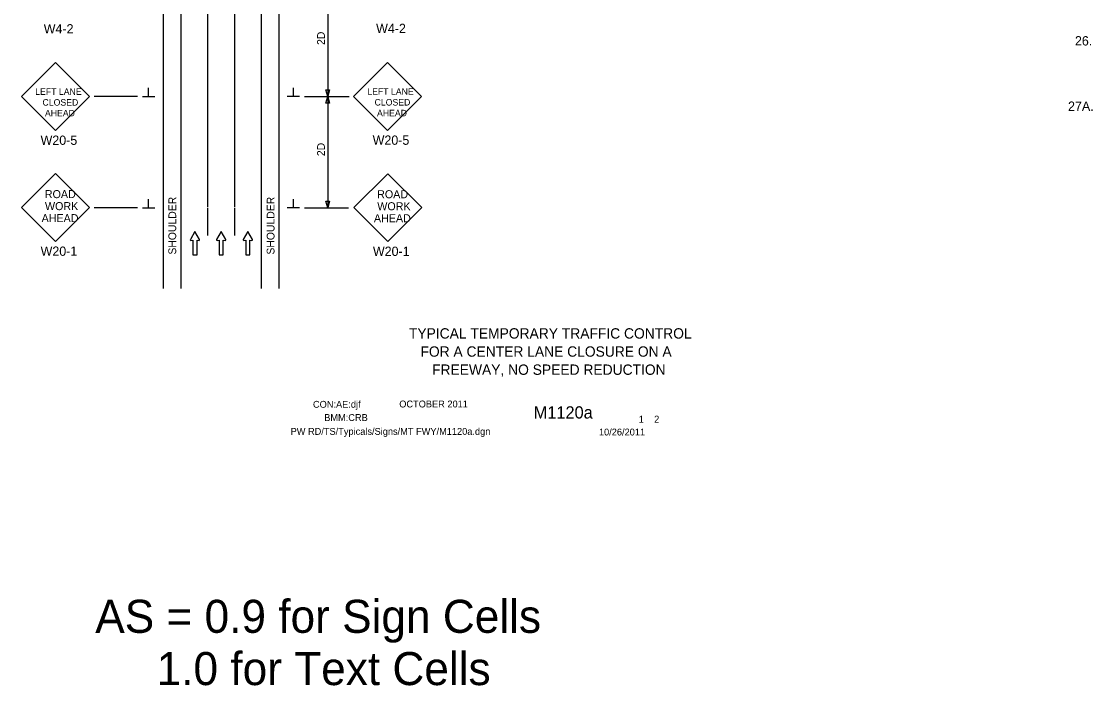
# Model space of a CAD drawing. Extents: x 16595 to 19519, y 6994 to 8256.
# Drawn here: x 16828 to 17792, y 6994 to 7592 of the extents above; entities that cross this region are included whole.
import ezdxf

# ---------------------------------------------------------------- set-up
doc = ezdxf.new("R2010")
doc.units = 0
for name, color, linetype in [('ALI_LEGAL_EX', 7, 'Continuous'), ('BORDER', 7, 'Continuous'), ('BORDER_SIGNAL_WO', 7, 'Continuous'), ('MT_SCRATCH_LEVEL_E', 7, 'Continuous'), ('PAVT_EDGE_EX', 7, 'Continuous'), ('TRAFFIC_SIGNS_PR', 7, 'Continuous'), ('TYPICAL_TEXT_DIMEN_PR', 7, 'Continuous')]:
    doc.layers.add(name, color=color, linetype=linetype)

msp = doc.modelspace()

# ---------------------------------------------------------------- linework, layer by layer
at = {"layer": 'ALI_LEGAL_EX'}
for p, q in [((16995.95, 8243.16), (16995.95, 7425.02)), ((17019.95, 8243.16), (17019.95, 7425.02))]:
    msp.add_line(p, q, dxfattribs=at)
for points in [[(16995.95, 7524.26), (16995.95, 7499.26)], [(17019.95, 7524.26), (17019.95, 7499.26)], [(16995.95, 7424.26), (16995.95, 7399.26)], [(17019.95, 7424.26), (17019.95, 7399.26)]]:
    msp.add_lwpolyline(points, dxfattribs=at)
at = {"layer": 'MT_SCRATCH_LEVEL_E'}
for p, q in [((16984.51, 7402.8), (16980.4, 7395.56)), ((16988.65, 7395.56), (16984.51, 7402.8)), ((17008.06, 7402.8), (17003.94, 7395.56)), ((17012.2, 7395.56), (17008.06, 7402.8)), ((17032.13, 7402.8), (17028.01, 7395.56)), ((17036.27, 7395.56), (17032.13, 7402.8)), ((16980.88, 7394.87), (16982.66, 7395.19)), ((16982.66, 7395.19), (16982.66, 7381.93)), ((16986.4, 7381.93), (16986.4, 7395.19)), ((16986.4, 7395.19), (16988.17, 7394.87)), ((17004.43, 7394.87), (17006.2, 7395.19)), ((17006.2, 7395.19), (17006.2, 7381.93)), ((17009.94, 7381.93), (17009.94, 7395.19)), ((17009.94, 7395.19), (17011.72, 7394.87)), ((17028.5, 7394.87), (17030.27, 7395.19)), ((17030.27, 7395.19), (17030.27, 7381.93)), ((17034.02, 7381.93), (17034.02, 7395.19)), ((17034.02, 7395.19), (17035.79, 7394.87)), ((16982.66, 7381.93), (16986.4, 7381.93)), ((17006.2, 7381.93), (17009.94, 7381.93)), ((17030.27, 7381.93), (17034.02, 7381.93))]:
    msp.add_line(p, q, dxfattribs=at)
for centre, start, end in [((16980.8, 7395.33), 150.42484, 279.96381), ((16988.25, 7395.33), 260.03619, 29.77312), ((17004.35, 7395.33), 150.42484, 279.96381), ((17011.79, 7395.33), 260.03619, 29.77312), ((17028.42, 7395.33), 150.42484, 279.96381), ((17035.86, 7395.33), 260.03619, 29.77312)]:
    msp.add_arc(centre, 0.463, start, end, dxfattribs=at)
at = {"layer": 'PAVT_EDGE_EX'}
for p, q in [((16955.95, 8212.14), (16955.95, 7351.67)), ((16971.95, 8212.14), (16971.95, 7351.67)), ((17043.95, 8212.14), (17043.95, 7351.67)), ((17059.95, 8212.14), (17059.95, 7351.67))]:
    msp.add_line(p, q, dxfattribs=at)
at = {"layer": 'TRAFFIC_SIGNS_PR'}
for p, q in [((16858.97, 7554.71), (16828.42, 7524.16)), ((16889.51, 7524.16), (16858.97, 7554.71)), ((17157.67, 7554.79), (17127.13, 7524.24)), ((17188.22, 7524.24), (17157.67, 7554.79)), ((16828.42, 7524.16), (16858.97, 7493.62)), ((16858.97, 7493.62), (16889.51, 7524.16)), ((17127.13, 7524.24), (17157.67, 7493.7)), ((17157.67, 7493.7), (17188.22, 7524.24)), ((16859, 7454.93), (16828.45, 7424.38)), ((16889.54, 7424.38), (16859, 7454.93)), ((17157.92, 7454.83), (17127.37, 7424.29)), ((17188.46, 7424.29), (17157.92, 7454.83)), ((16828.45, 7424.38), (16859, 7393.83)), ((16859, 7393.83), (16889.54, 7424.38)), ((17127.37, 7424.29), (17157.92, 7393.74)), ((17157.92, 7393.74), (17188.46, 7424.29))]:
    msp.add_line(p, q, dxfattribs=at)
at = {"layer": 'TYPICAL_TEXT_DIMEN_PR'}
for p, q in [((17103.95, 7624.28), (17103.95, 7524.28)), ((16942.82, 7524.28), (16942.82, 7532.06)), ((17073.07, 7524.28), (17073.07, 7532.06)), ((17103.95, 7524.28), (17102.38, 7530.14)), ((17102.38, 7530.14), (17103.95, 7530.14)), ((17103.95, 7530.14), (17105.52, 7530.14)), ((17105.52, 7530.14), (17103.95, 7524.28)), ((16932.95, 7524.28), (16893.95, 7524.28)), ((16937.2, 7524.28), (16948.45, 7524.28)), ((17078.7, 7524.28), (17067.45, 7524.28)), ((17082.95, 7524.28), (17123.24, 7524.28)), ((17102.38, 7518.42), (17103.95, 7524.28)), ((17103.95, 7518.42), (17102.38, 7518.42)), ((17103.95, 7524.28), (17103.95, 7424.28)), ((17103.95, 7524.28), (17105.52, 7518.42)), ((17105.52, 7518.42), (17103.95, 7518.42)), ((16942.82, 7424.28), (16942.82, 7432.06)), ((17073.07, 7424.28), (17073.07, 7432.06)), ((17103.95, 7424.28), (17102.38, 7430.14)), ((17102.38, 7430.14), (17103.95, 7430.14)), ((17103.95, 7430.14), (17105.52, 7430.14)), ((17105.52, 7430.14), (17103.95, 7424.28)), ((16932.95, 7424.28), (16893.95, 7424.28)), ((16937.2, 7424.28), (16948.45, 7424.28)), ((17078.7, 7424.28), (17067.45, 7424.28)), ((17082.95, 7424.28), (17122.72, 7424.28))]:
    msp.add_line(p, q, dxfattribs=at)

# ---------------------------------------------------------------- texts
at = {"layer": 'BORDER'}
for s, p in [('TYPICAL TEMPORARY TRAFFIC CONTROL', (17177.02, 7306.53)), ('FOR A CENTER LANE CLOSURE ON A', (17187.36, 7290.23)), ('FREEWAY, NO SPEED REDUCTION', (17197.83, 7273.93))]:
    msp.add_text(s, height=9.3, dxfattribs=at).set_placement(p)
at = {"layer": 'BORDER_SIGNAL_WO'}
for s, height, p in [('CON:AE:djf  ', 6.2, (17090.69, 7244.31)), ('    OCTOBER 2011    ', 6.2, (17159.08, 7244.59)), ('BMM:CRB   ', 6.2, (17100.81, 7232.42)), ('    M1120a   ', 11, (17272.86, 7234.63)), (' 1    2 ', 6.2, (17381.45, 7230.95)), ('PW RD/TS/Typicals/Signs/MT FWY/M1120a.dgn      ', 6.2, (17070.55, 7219.96)), ('10/26/2011    ', 6.2, (17347.93, 7219.38)), ('AS = 0.9 for Sign Cells', 29.7271, (16894.83, 7041.87)), ('     1.0 for Text Cells', 29.7271, (16894.83, 6994.87))]:
    msp.add_text(s, height=height, dxfattribs=at).set_placement(p)
at = {"layer": 'TRAFFIC_SIGNS_PR'}
for s, height, p in [('W4-2', 8.37, (16848.5, 7580.94)), ('W4-2', 8.37, (17147.49, 7581.28)), ('LEFT LANE', 5.85, (16840.83, 7525.73)), ('LEFT LANE', 5.85, (17139.54, 7525.81)), ('CLOSED', 5.85, (16847.39, 7516.06)), ('CLOSED', 5.85, (17146.1, 7516.14)), ('AHEAD', 5.85, (16849.58, 7506.38)), ('AHEAD', 5.85, (17148.29, 7506.46)), ('W20-5', 8.37, (16845.66, 7480.75)), ('W20-5', 8.37, (17144.37, 7480.83)), ('ROAD', 7.2, (16849.48, 7432.86)), ('ROAD', 7.2, (17148.4, 7432.76)), ('WORK', 7.2, (16849.6, 7422.06)), ('WORK', 7.2, (17148.52, 7421.96)), ('AHEAD', 7.2, (16846.58, 7411.26)), ('AHEAD', 7.2, (17145.5, 7411.16)), ('W20-1', 8.37, (16845.69, 7380.96)), ('W20-1', 8.37, (17144.61, 7380.87))]:
    msp.add_text(s, height=height, dxfattribs=at).set_placement(p)
at = {"layer": 'TYPICAL_TEXT_DIMEN_PR'}
for s, p in [('2D', (17101.39, 7570.64)), ('2D', (17101.39, 7470.64)), ('SHOULDER', (16967.63, 7382.05)), ('SHOULDER', (17056.07, 7382.05))]:
    msp.add_text(s, height=7, rotation=90, dxfattribs=at).set_placement(p)
for s, p in [('26.', (17776.09, 7570.14)), ('27A.', (17769.88, 7511.34))]:
    msp.add_text(s, height=8.4, dxfattribs=at).set_placement(p)

doc.saveas('drawing.dxf')
